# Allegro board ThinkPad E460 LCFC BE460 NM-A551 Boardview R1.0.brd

Outline 300.1 x 178 mm; copper layers: TOP, GND1, IN1, IN2, VCC, IN3, GND2, BOTTOM. Coordinates in mm from the lower left corner of the outline.
Outline path: 0,164 arc(0.59,165.41) 2,166 14.7,166 arc(15.41,166.29) 15.7,167 15.7,172 arc(16.29,173.41) 17.7,174 22.2,174 arc(22.55,174.15) 22.7,174.5 22.7,177 arc(22.99,177.71) 23.7,178 29.2,178 arc(29.55,177.85) 29.7,177.5 29.7,177.4 arc(29.85,177.05) 30.2,176.9 39.2,176.9 arc(39.55,177.05) 39.7,177.4 39.7,177.5 arc(39.85,177.85) 40.2,178 71.75,178 arc(72.46,177.71) 72.75,177 72.75,176 arc(73.04,175.29) 73.75,175 85.75,175 arc(86.46,175.29) 86.75,176 86.75,177 arc(87.04,177.71) 87.75,178 245.7,178 arc(247.11,177.41) 247.7,176 247.7,175 arc(247.99,174.29) 248.7,174 250.2,174 arc(250.91,173.71) 251.2,173 251.2,167 arc(251.49,166.29) 252.2,166 271.68,166 arc(273.1,165.41) 273.68,164 273.68,137.5 arc(273.98,136.79) 274.68,136.5 293.18,136.5 arc(294.6,135.91) 295.18,134.5 295.18,133.3 arc(296.16,130.34) 298.7,128.53 arc(298.95,128.34) 299.05,128.05 299.05,126.15 arc(298.9,125.8) 298.55,125.65 286.55,125.65 286.55,123.9 arc(286.7,123.55) 287.05,123.4 287.35,123.4 287.35,111.49 287.05,111.49 arc(286.7,111.34) 286.55,110.99 286.55,96.75 298.05,96.75 arc(298.4,96.6) 298.55,96.25 298.55,94.45 arc(298.26,93.74) 297.55,93.45 295.7,93.45 arc(294.35,92.1) 295.7,90.75 297.55,90.75 arc(298.26,90.46) 298.55,89.75 298.55,87.9 arc(298.4,87.55) 298.05,87.4 290.3,87.4 arc(289.8,87.9) 289.3,87.4 289.3,70.6 arc(289.8,70.1) 290.3,70.6 298.4,70.6 arc(298.75,70.45) 298.9,70.1 298.9,65.75 arc(298.75,65.4) 298.4,65.25 290.85,65.25 arc(290.4,64.8) 290.85,64.35 290.85,50.65 arc(290.4,50.2) 290.85,49.75 299.1,49.75 300.1,48.75 300.1,40.8 299.1,39.8 288.37,39.8 arc(287.87,39.3) 288.37,38.8 288.37,27.2 arc(287.87,26.7) 288.37,26.2 297.55,26.2 298.55,25.2 298.55,18.8 297.55,17.8 288.37,17.8 arc(287.87,17.3) 288.37,16.8 288.37,5.2 arc(287.87,4.7) 288.37,4.2 298.05,4.2 299.05,3.2 299.05,2 arc(298.46,0.59) 297.05,0 285.41,0 arc(284,0.59) 283.41,2 283.41,5.5 arc(282.82,6.91) 281.41,7.5 276.61,7.5 arc(275.2,8.09) 274.61,9.5 274.61,17.5 arc(274.9,18.21) 275.61,18.5 275.9,18.5 arc(276.25,18.65) 276.4,19 276.4,24 arc(276.25,24.35) 275.9,24.5 275.61,24.5 arc(274.9,24.79) 274.61,25.5 274.61,68.97 arc(274.33,69.69) 273.61,70 261.04,70 arc(260.33,70.29) 260.04,71 260.04,71.99 arc(259.89,72.35) 259.53,72.5 223.37,72.5 arc(222.98,72.34) 222.85,71.94 222.85,71.04 arc(222.54,70.28) 221.78,70 198.69,70 arc(197.96,69.72) 197.65,69 197.65,48.5 arc(197.06,47.09) 195.65,46.5 68.7,46.5 arc(67.99,46.21) 67.7,45.5 arc(67.41,44.79) 66.7,44.5 57.7,44.5 arc(56.99,44.79) 56.7,45.5 arc(56.41,46.21) 55.7,46.5 29.7,46.5 arc(28.29,47.09) 27.7,48.5 27.7,52.74 arc(28.14,54) 29.28,54.7 arc(40.89,59.22) 50.27,67.43 arc(50.88,67.79) 51.58,67.65 52.23,67.24 arc(52.41,67.14) 52.6,67.04 arc(56.47,68.36) 55.43,72.32 55.31,72.39 54.83,72.7 arc(54.4,73.27) 54.46,73.99 54.46,73.99 arc(52.82,108.97) 22.22,126 13.2,126 arc(12.05,126.37) 11.31,127.33 arc(11.28,127.42) 11.24,127.5 arc(10.87,127.87) 10.37,128 5.2,128 arc(4.85,128.15) 4.7,128.5 arc(4.55,128.85) 4.2,129 2,129 arc(0.59,129.59) 0,131 0,164

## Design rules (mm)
net group 5_20: nets +3VALW_LOGO +3VS_CMOS
net group +1.65V_LDO: nets +1.65V_LDO +3V_LDO
net group +3V_SPI: nets SPI_IO2 SPI_IO3
net group +3VL_AVCC: nets +3VL_AVCC EC_AGND
net group +5VS_CLASSD: nets +5VS_CLASSD N57924109
net group +5VS_HDMI: nets HDMI_CLK_CON HDMI_DAT_CON
net group ACIN: nets ACIN ACPRN
net group CLK-12: nets CLK_PCI_EC PCH_PCI_CLK_R
net group CPU_EDP_AUX: nets CPU_EDP_AUX CPU_EDP_AUX_CON
net group CPU_EDP_AUX#: nets CPU_EDP_AUX# CPU_EDP_AUX#_CON
net group CPU_EDP_TX0+: nets CPU_EDP_TX0+ CPU_EDP_TX0+_CON
net group CPU_EDP_TX0-: nets CPU_EDP_TX0- CPU_EDP_TX0-_CON
net group CPU_EDP_TX1+: nets CPU_EDP_TX1+ CPU_EDP_TX1+_CON
net group CPU_EDP_TX1-: nets CPU_EDP_TX1- CPU_EDP_TX1-_CON
net group DDRA_DQTODQS0: nets DDR_A_DQS0 DDR_A_DQS#0
net group DDRA_DQTODQS3: nets DDR_A_DQS3 DDR_A_DQS#3
net group DDRA_DQTODQS4: nets DDR_A_DQS4 DDR_A_DQS#4
net group DDRA_DQTODQS5: nets DDR_A_DQS5 DDR_A_DQS#5
net group DDRA_DQTODQS6: nets DDR_A_DQS6 DDR_A_DQS#6
net group DDRA_DQTODQS7: nets DDR_A_DQS7 DDR_A_DQS#7
net group DDRB_DQTODQS0: nets DDR_B_DQS0 DDR_B_DQS#0
net group DDRB_DQTODQS1: nets DDR_B_DQS1 DDR_B_DQS#1
net group DDRB_DQTODQS2: nets DDR_B_DQS2 DDR_B_DQS#2
net group DDRB_DQTODQS3: nets DDR_B_DQS3 DDR_B_DQS#3
net group DDRB_DQTODQS4: nets DDR_B_DQS4 DDR_B_DQS#4
net group DDRB_DQTODQS5: nets DDR_B_DQS5 DDR_B_DQS#5
net group DDRB_DQTODQS6: nets DDR_B_DQS6 DDR_B_DQS#6
net group DDRB_DQTODQS7: nets DDR_B_DQS7 DDR_B_DQS#7
net group DIFFPAIR13: nets USB20_N5 USB20_P5
net group DIFFPAIR20: nets CLK_PCIE_LAN CLK_PCIE_LAN#
net group DIFFPAIR21: nets CLK_PCIE_CR CLK_PCIE_CR#
net group DIFFPAIR22: nets CLK_PCIE_VGA CLK_PCIE_VGA#
net group DIFFPAIR23: nets CLK_PCIE_WLAN CLK_PCIE_WLAN#
net group DIFFPAIR94: nets HDMI_CLK HDMI_DAT
net group DIFFPAIR100: nets USB3P4_RXN USB3P4_RXP
net group DIFFPAIR101: nets N57771580 N57771583
net group DIFFPAIR104: nets PCIE3_PTX_DRX_N2 PCIE3_PTX_DRX_P2
net group DIFFPAIR105: nets PCIE4_PTX_DRX_N3 PCIE4_PTX_DRX_P3
net group DIFFPAIR106: nets PCIE1_PTX_DRX_N0 PCIE1_PTX_DRX_P0
net group DIFFPAIR107: nets PCIE2_PTX_DRX_N1 PCIE2_PTX_DRX_P1
net group DIFFPAIR108: nets PCIE4_CTX_C_DRX_N PCIE4_CTX_C_DRX_P
net group DISP_A0_L_C: nets DISP_A0N_L_C DISP_A0P_L_C
net group DISP_A1_L_C: nets DISP_A1N_L_C DISP_A1P_L_C
net group DOCK_AUXN: nets DOCK_AUXN DOCK_AUXN_RE
net group DOCK_AUXP: nets DOCK_AUXP DOCK_AUXP_RE
net group DOCK_TX0+: nets DOCK_TX0+ DOCK_TX0+_RE
net group DOCK_TX0-: nets DOCK_TX0- DOCK_TX0-_RE
net group DOCK_TX1: nets DOCK_TX1+ DOCK_TX1-
net group DOCK_TX1_R: nets DOCK_TX1+_R DOCK_TX1-_R
net group DOCK_TX_RE: nets DOCK_TX1+_RE DOCK_TX1-_RE
net group DP: nets DOCK_TX0+_R DOCK_TX0-_R
net group DP_RE_DP0: nets DP_RE_DP0N DP_RE_DP0P
net group DP_RE_DP1: nets DP_RE_DP1N DP_RE_DP1P
net group DP_USB3P4_TX: nets USB3P4_TXN USB3P4_TXP
net group DP_USB20_N3_OD: nets USB20_N3_OD USB20_P3_OD
net group GPIO15: nets GPIO15 SVI2_SVD
net group GPIO20: nets GPIO20 SVI2_SVC
net group HDA_SDOUT: nets HDA_SDOUT ME_FLASH
net group HDMI_TX0+_CON: nets HDMI_TX0+_CON HDMI_TX0+_REOUT
net group HDMI_TX0+_REIN: nets H_HDMI_TX0+ HDMI_TX0+_REIN
net group HDMI_TX0-_CON: nets HDMI_TX0-_CON HDMI_TX0-_REOUT
net group HDMI_TX0-_REIN: nets H_HDMI_TX0- HDMI_TX0-_REIN
net group HDMI_TX1+_CON: nets HDMI_TX1+_CON HDMI_TX1+_REOUT
net group HDMI_TX1+_REIN: nets H_HDMI_TX1+ HDMI_TX1+_REIN
net group HDMI_TX1-_CON: nets HDMI_TX1-_CON HDMI_TX1-_REOUT
net group HDMI_TX1-_REIN: nets H_HDMI_TX1- HDMI_TX1-_REIN
net group HDMI_TX2+_CON: nets HDMI_TX2+_CON HDMI_TX2+_REOUT
net group HDMI_TX2+_REIN: nets H_HDMI_TX2+ HDMI_TX2+_REIN
net group HDMI_TX2-_CON: nets HDMI_TX2-_CON HDMI_TX2-_REOUT
net group HDMI_TX2-_REIN: nets H_HDMI_TX2- HDMI_TX2-_REIN
net group HDMI_TXC+_CON: nets HDMI_TXC+_CON HDMI_TXC+_REOUT
net group HDMI_TXC+_REIN: nets H_HDMI_TXC+ HDMI_TXC+_REIN
net group HDMI_TXC-_CON: nets HDMI_TXC-_CON HDMI_TXC-_REOUT
net group HDMI_TXC-_REIN: nets H_HDMI_TXC- HDMI_TXC-_REIN
net group HP_OUTL: nets HP_OUTL N58599815
net group HP_OUTR: nets HP_OUTR N57919452
net group LAN_WAKE#: nets LAN_WAKE# LAN_WAKE#_R
net group N13756593: nets N13756593 N13756601
net group N13756597: nets N13756597 N13756610
net group N57924172: nets N57924172 N57924174
net group PC_BEEP: nets N57919838 PC_BEEP
net group PCH_PWROK: nets PCH_PWROK PWROK
net group PCIE3_CTX_C_DRX_N: nets PCIE3_CTX_C_DRX_N PCIE3_CTX_DRX_N
net group PCIE3_CTX_C_DRX_P: nets PCIE3_CTX_C_DRX_P PCIE3_CTX_DRX_P
net group PCIE4_CRX_DTX_N: nets PCIE4_CRX_DTX_N PCIE4_CRX_DTX_N_C
net group PCIE4_CRX_DTX_P: nets PCIE4_CRX_DTX_P PCIE4_CRX_DTX_P_C
net group PCIE4_CTX_C_DRX_: nets PCIE4_CTX_DRX_N PCIE4_CTX_DRX_P
net group PCIE6_CTX_C_DRX_N: nets PCIE6_CTX_C_DRX_N PCIE6_CTX_DRX_N
net group PCIE6_CTX_C_DRX_P: nets PCIE6_CTX_C_DRX_P PCIE6_CTX_DRX_P
net group PCIE_CRX_C_GTX_N0: nets PCIE_CRX_C_GTX_N0 PCIE_CRX_GTX_N0
net group PCIE_CRX_C_GTX_N1: nets PCIE_CRX_C_GTX_N1 PCIE_CRX_GTX_N1
net group PCIE_CRX_C_GTX_N2: nets PCIE_CRX_C_GTX_N2 PCIE_CRX_GTX_N2
net group PCIE_CRX_C_GTX_N3: nets PCIE_CRX_C_GTX_N3 PCIE_CRX_GTX_N3
net group PCIE_CRX_C_GTX_P0: nets PCIE_CRX_C_GTX_P0 PCIE_CRX_GTX_P0
net group PCIE_CRX_C_GTX_P1: nets PCIE_CRX_C_GTX_P1 PCIE_CRX_GTX_P1
net group PCIE_CRX_C_GTX_P2: nets PCIE_CRX_C_GTX_P2 PCIE_CRX_GTX_P2
net group PCIE_CRX_C_GTX_P3: nets PCIE_CRX_C_GTX_P3 PCIE_CRX_GTX_P3
net group PCIE_CTX_C_GRX_0: nets PCIE_CTX_C_GRX_N0 PCIE_CTX_C_GRX_P0
net group PCIE_CTX_C_GRX_1: nets PCIE_CTX_C_GRX_N1 PCIE_CTX_C_GRX_P1
net group PCIE_CTX_C_GRX_2: nets PCIE_CTX_C_GRX_N2 PCIE_CTX_C_GRX_P2
net group PCIE_CTX_C_GRX_3: nets PCIE_CTX_C_GRX_N3 PCIE_CTX_C_GRX_P3
net group PCIE_WLAN: nets PCIE3_CRX_DTX_N PCIE3_CRX_DTX_P
net group PORTB_L: nets N57919402 PORTB_L
net group PS8713_RX1_C_N: nets PS8713_RX1_C_N USB3P1_RXN_CON
net group PS8713_RX1_C_P: nets PS8713_RX1_C_P USB3P1_RXP_CON
net group PS8713_RX1_R: nets PS8713_RX1_N_R PS8713_RX1_P_R
net group PS8713_RX2_C_N: nets PS8713_RX2_C_N USB30_RX_N2_CON
net group PS8713_RX2_C_P: nets PS8713_RX2_C_P USB30_RX_P2_CON
net group REMOTE1: nets REMOTE1+ REMOTE1-
net group REMOTE2: nets REMOTE2+ REMOTE2-
net group SATA_PRX_C_DTX_N0: nets SATA_PRX_C_DTX_N0 SATA_PRX_DTX_N0
net group SATA_PRX_C_DTX_P0: nets SATA_PRX_C_DTX_P0 SATA_PRX_DTX_P0
net group SATA_PTX_C_DRX_N0: nets SATA_PTX_C_DRX_N0 SATA_PTX_DRX_N0
net group SATA_PTX_C_DRX_P0: nets SATA_PTX_C_DRX_P0 SATA_PTX_DRX_P0
net group TP_RESET: nets TP_RESET TP_REST
net group USB3_RX4_OD: nets USB3_RX4_N_OD USB3_RX4_P_OD
net group USB3_TX1_REOUT: nets USB3_TX1+_REOUT USB3_TX1-_REOUT
net group USB3_TX4_OD: nets USB3_TX4_N_OD USB3_TX4_P_OD
net group USB3P1_RX: nets USB3P1_RXN USB3P1_RXP
net group USB3P1_RX_R: nets USB3P1_RXN_R USB3P1_RXP_R
net group USB3P1_TX: nets USB3_TX1+_REIN USB3_TX1-_REIN
net group USB3P1_TX1: nets USB3P1_TXN USB3P1_TXP
net group USB3P1_TX_C: nets USB3P1_TXN_C USB3P1_TXP_C
net group USB3P1_TX_CON: nets USB3P1_TXN_CON USB3P1_TXP_CON
net group USB3P1_TX_R: nets USB3P1_TXN_R USB3P1_TXP_R
net group USB3P2_RX_R: nets USB3P2_RXN_R USB3P2_RXP_R
net group USB3P2_RXN: nets N57772807 USB3P2_RXN
net group USB3P2_RXP: nets N57772804 USB3P2_RXP
net group USB3P2_TX_R: nets USB3P2_TXN_R USB3P2_TXP_R
net group USB3P2_TXN: nets USB3_TX2-_REIN USB3P2_TXN
net group USB3P2_TXP: nets USB3_TX2+_REIN USB3P2_TXP
net group USB3P4_RX_C: nets USB3P4_RXN_C USB3P4_RXP_C
net group USB3P4_TX_C: nets USB3P4_TXN_C USB3P4_TXP_C
net group USB20_7_COMS: nets USB20_N6_CMOS USB20_P6_CMOS
net group USB20_N0: nets USB20_N0 USB20_N0_CON
net group USB20_N1: nets USB20_N1 USB20_N1_CON
net group USB20_N2_C: nets USB20_N2_C USB20_N2_CONN
net group USB20_P0: nets USB20_P0 USB20_P0_CON
net group USB20_P1: nets USB20_P1 USB20_P1_CON
net group USB20_P2_C: nets USB20_P2_C USB20_P2_CONN
net group USB30_TX_2_CON: nets USB3_TX2+_REOUT USB3_TX2-_REOUT
net group USB30_TX_N2_CON: nets USB3P2_TXN_C USB30_TX_N2_CON
net group USB30_TX_P2_CON: nets USB3P2_TXP_C USB30_TX_P2_CON
net group VCC_SENSE: nets N62685817 VCC_SENSE
net group VCCGT_SENSE: nets N62959739 VCCGT_SENSE
net group VSS_SENSE: nets N62687376 VSS_SENSE
net group VSUM: nets VSUM+ VSUM-
net group +3VALW_LAN: nets N19577505
net group +VCC_ST: nets THRMTRIP#
net group AUDIO_IHDA: nets HDA_BCLK HDA_RST# HDA_SYNC PCH_HDA_RST# PCH_HDA_SDIN0 PCH_HDA_SDIN0_R PCH_HDA_SDOUT PCH_HDA_SYNC
net group BEEP#: nets BEEP# N57919809 PCH_BEEP
net group CONTROL_LINK: nets CL_CLK_WLAN
net group DIFFPAIR77: nets USB20_P2
net group DMIC-12: nets DMIC_CLK DMIC_DATA MIC_CLK_R
net group DOCK_AUXN_CONN: nets DOCK_AUXN_CONN DOCK_AUXN_R DP_RE_AUXN
net group DOCK_AUXP_CONN: nets DOCK_AUXP_CONN DOCK_AUXP_R DP_RE_AUXP
net group EDP: nets CPU_EDP_HPD
net group FBA_RST#: nets FBA_RST# N13756920 N13756934
net group LAN2: nets RJ45_TXD0N RJ45_TXD0P RJ45_TXD1N RJ45_TXD1P RJ45_TXD2N RJ45_TXD2P RJ45_TXD3N RJ45_TXD3P
net group PCIE6_CRX_DTX_: nets PCIE6_CRX_DTX_P
net group PCIE_CR: nets PCIE6_CRX_DTX_N
net group PWR: nets +3VALW_GS +3VS_VDDIO +5VS_AVDD AOU_CTL3 APDIN P3 SPI_IO2_4MB SPI_IO2_8MB SPI_IO3_4MB SPI_IO3_8MB VSYSTEM
net group RTC: nets PCH_RTCRST# PCH_RTCX1 PCH_RTCX2
net group S8: nets SUSCLK_32K
net group S12: nets CLKREQ_PCIE5_CR# VR_SVID_ALRT#_R VR_SVID_CLK VR_SVID_DAT
net group S13.5: nets DDR3_DRAMRST# H_PROCHOT_EC VR_HOT# VR_HOT#_R
net group S18: nets H_PECI H_THERMTRIP# PECI
net group S20: nets DIFFCLK_BIASREF SM_RCOMP0 SM_RCOMP1 SM_RCOMP2
net group SMBUS: nets EC_SMB_CK1 EC_SMB_CK3 EC_SMB_DA1 EC_SMB_DA3 PCH_SMB_CLK PCH_SMB_DATA PM_SMB_CLK PM_SMB_DAT SMBCLK SMBDAT
net group SPI-12: nets SPI_CLK SPI_CLK_4MB SPI_CLK_8MB SPI_FSCK
net group SPK_L1-: nets SPK_L1-
net group SPK_L2+: nets SPK_L2+
net group SPK_R1-: nets SPK_R1-
net group SPK_R2+: nets SPK_R2+
net group USB20: nets USB20_N2 USB20_N3 USB20_N4_TPANEL USB20_N4_TPANEL_C USB20_N6 USB20_N8 USB20_P3 USB20_P4_TPANEL USB20_P4_TPANEL_C USB20_P6 USB20_P8
net group USB30: nets PS8713_RX2_N_R PS8713_RX2_P_R USB3_TX4_N_C USB3_TX4_P_C USB3P3_RXN USB3P3_RXN_C USB3P3_RXP USB3P3_RXP_C USB3P3_TXN USB3P3_TXN_C USB3P3_TXP USB3P3_TXP_C USB3P4_RE_RXN USB3P4_RE_RXN_R USB3P4_RE_RXP USB3P4_RE_RXP_R USB3P4_RE_TXN USB3P4_RE_TXN_R USB3P4_RE_TXP USB3P4_RE_TXP_R USB3P4_RXN_R USB3P4_RXP_R USB3P4_TXN_R USB3P4_TXP_R

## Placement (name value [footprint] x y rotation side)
C1  0.1U_0402_10V7-K  [C_0402]  42.15 127.59 180 top
C2  2200P_0402_50V7-K  [C_0402]  39.48 126.78 270 top
C3  2200P_0402_50V7-K  [C_0402]  39.86 124.75 270 top
C4  100P_0402_50V8-J  [C_0402]  163.02 110.37 0 top
C5  100P_0402_50V8-J  [C_0402]  4.81 132.37 270 top
C8  1U_0402_6.3V6-K  [C_0402]  70.97 119.03 0 bottom
C9  4.7U_0603_10V6-K  [C_0603]  72.63 116.62 0 bottom
C10  1U_0402_6.3V6-K  [C_0402]  65.91 123.71 135 bottom
C11  4.7U_0603_10V6-K  [C_0603]  62.35 117.62 315 bottom
C12  4.7U_0805_25V6-K  [C_0805]  61.99 111.95 45 bottom
C13  0.1U_0402_10V7-K  [C_0402]  55.42 121.77 225 bottom
C14  0.1U_0402_10V7-K  [C_0402]  54.79 122.4 225 bottom
C15  0.1U_0402_10V7-K  [C_0402]  54.15 123.04 225 bottom
C16  0.1U_0402_10V7-K  [C_0402]  53.52 123.67 225 bottom
C17  0.1U_0402_10V7-K  [C_0402]  56.82 120.37 225 bottom
C18  0.1U_0402_10V7-K  [C_0402]  56.18 121.01 225 bottom
C19  10U_0805_10V6-K  [C_0805]  251.57 80.33 90 bottom
C20  10U_0805_10V6-K  [C_0805]  245.98 80.3 90 bottom
C21  1U_0402_10V6K  [C_0402]  249.28 80.17 90 bottom
C22  0.1U_0402_10V7-K  [C_0402]  250.17 80.17 90 bottom
C23  1000P_0402_50V7-K  [C_0402]  247.5 80.17 90 bottom
C24  .01U_0402_16V7-K  [C_0402]  226.93 81.06 270 bottom
C25  .01U_0402_16V7-K  [C_0402]  227.95 81.06 270 bottom
C26  .01U_0402_16V7-K  [C_0402]  230.36 81.06 270 bottom
C27  .01U_0402_16V7-K  [C_0402]  231.38 81.06 270 bottom
C28  0.1U_0402_10V7-K  [C_0402]  207.88 99.52 90 top
C29  .01U_0402_16V7-K  [C_0402]  205.07 92.05 180 top
C30  0.1U_0402_10V7-K  [C_0402]  201.89 97 0 top
C31  0.1U_0402_10V7-K  [C_0402]  201.73 94.77 0 top
C32  0.1U_0402_10V7-K  [C_0402]  201.91 95.71 0 top
C33  0.1U_0402_10V7-K  [C_0402]  201.71 93.45 0 top
C34  0.1U_0402_10V7-K  [C_0402]  225.25 99.47 90 top
C35  .01U_0402_16V7-K  [C_0402]  221.06 91.37 270 top
C36  0.1U_0402_10V7-K  [C_0402]  219.03 97.44 0 top
C37  0.1U_0402_10V7-K  [C_0402]  219.06 96.12 0 top
C38  0.1U_0402_10V7-K  [C_0402]  217.43 92.44 90 top
C39  0.1U_0402_10V7-K  [C_0402]  219.54 92.45 90 top
C40  .01U_0402_16V7-K  [C_0402]  275.07 125.27 90 bottom
C41  1U_0402_6.3V6-K  [C_0402]  275.96 125.27 90 bottom
C44  100P_0402_50V8J  [C_0402]  123.93 69.43 90 bottom
C45  100P_0402_50V8J  [C_0402]  124.95 69.43 90 bottom
C50  0.1U_0402_10V6-K  [C_0402]  124.99 157.27 270 top
C51  10U_0603_6.3V6-M  [C_0603]  123.94 157.22 270 top
C52  0.1U_0402_10V7-K  [C_0402]  190.15 74.07 0 top
C53  0.1U_0402_10V7-K  [C_0402]  296.58 42.32 0 top
C67  10U_0603_6.3V6-M  [C_0603]  249.6 152.09 180 top
C68  0.1U_0402_10V7-K  [C_0402]  141.82 69.3 270 top
C69  1U_0402_6.3V6-K  [C_0402]  219.58 138.15 90 top
C70  0.1U_0402_10V7-K  [C_0402]  221.34 130.79 270 top
C71  1000P_0402_25V7-K  [C_0402]  218.8 133.08 270 top
C72  100P_0402_50V8-J  [C_0402]  217.91 133.08 270 top
C73  1U_0402_6.3V6-K  [C_0402]  217.04 138.1 90 top
C74  0.1U_0402_10V7-K  [C_0402]  216.92 130.11 270 top
C75  .01U_0402_16V7-K  [C_0402]  268.28 129.83 180 top
C85  0.1U_0402_10V7-K  [C_0402]  272.32 114.33 0 top
C86  0.1U_0402_10V7-K  [C_0402]  272.32 115.22 0 top
C115  0.1U_0402_10V7-K  [C_0402]  253.52 154.08 0 top
C116  0.1U_0402_10V7-K  [C_0402]  253.52 153.19 0 top
C118  1000P_0402_50V7-K  [C_0402]  279.89 30.18 90 bottom
C119  0.1U_0402_10V7-K  [C_0402]  279.76 21.32 270 bottom
C120  1000P_0402_50V7-K  [C_0402]  283.39 25.94 180 bottom
C121  0.1U_0402_10V7-K  [C_0402]  277.4 37.95 90 bottom
C122  0.1U_0402_10V7-K  [C_0402]  277.4 39.78 270 bottom
C123  150U_B2_6.3VM_R35M  [C_B2]  282.43 28.86 270 bottom
C124  0.1U_0402_10V7-K  [C_0402]  278.87 37.93 90 bottom
C125  0.1U_0402_10V7-K  [C_0402]  277.71 17.71 90 bottom
C126  0.1U_0402_10V7-K  [C_0402]  279.23 17.66 90 bottom
C127  470P_0402_50V7-K  [C_0402]  279.33 26.32 180 bottom
C128  150U_B2_6.3VM_R35M  [C_B2]  279.75 9.95 0 top
C129  470P_0402_50V7-K  [C_0402]  283.32 10.83 90 bottom
C130  0.1U_0402_10V7-K  [C_0402]  278.87 39.76 270 bottom
C131  0.1U_0402_10V7-K  [C_0402]  277.71 19.54 270 bottom
C132  0.1U_0402_10V7-K  [C_0402]  279.23 19.49 270 bottom
C174  47P_0402_50V8-J  [C_0402]  60.62 113.75 45 bottom
C175  2200P_0402_50V7-K  [C_0402]  61.25 113.12 45 bottom
C176  47P_0402_50V8-J  [C_0402]  58.71 115.66 45 bottom
C177  2200P_0402_50V7-K  [C_0402]  61.63 116.69 315 bottom
C178  47P_0402_50V8-J  [C_0402]  72.63 114.59 0 bottom
C179  2200P_0402_50V7-K  [C_0402]  72.63 115.48 0 bottom
C180  2200P_0402_50V7-K  [C_0402]  57.39 116.89 45 bottom
C181  47P_0402_50V8-J  [C_0402]  59.14 119.04 45 bottom
C182  47P_0402_50V8-J  [C_0402]  267.52 154.46 180 top
C183  2200P_0402_50V7-K  [C_0402]  269.53 154.46 0 top
C184  0.1U_0402_10V7-K  [C_0402]  266.01 117.85 270 top
C185  0.1U_0402_10V7-K  [C_0402]  261.03 123.62 0 top
C186  0.1U_0402_10V7-K  [C_0402]  261.03 122.22 0 top
C187  0.1U_0402_10V7-K  [C_0402]  261.03 121.33 0 top
C188  0.1U_0402_10V7-K  [C_0402]  261.03 119.93 0 top
C189  .01U_0402_16V7-K  [C_0402]  269.49 125.7 90 top
C194  47UF_0805_6.3V  [C_0805]  104.78 128.65 180 top
C197  0.1U_0201_6.3V6K  [C_0201]  119.75 132.04 90 top
C200  0.1U_0201_6.3V6K  [C_0201]  114.14 128.02 90 top
C201  0.1U_0201_6.3V6K  [C_0201]  115.33 128.23 90 top
C202  2200P_0402_50V7-K  [C_0402]  253.87 80.62 90 bottom
C203  47P_0402_50V8-J  [C_0402]  252.98 80.62 90 bottom
C204  2200P_0402_50V7-K  [C_0402]  239.06 80.18 0 bottom
C205  47P_0402_50V8-J  [C_0402]  242 80.18 180 bottom
C206  2200P_0402_50V7-K  [C_0402]  57.96 110.48 315 top
C207  2200P_0402_50V7-K  [C_0402]  72.56 117.65 0 bottom
C747  2200P_0402_25V7-K  [C_0402]  76.49 118.02 0 top
C748  0.1U_0402_6.3V7-K  [C_0402]  74.62 114.52 180 top
C749  10U_0402_6.3V  [C_0402]  78.63 114.45 180 top
C750  1U_0402_6.3V6-K  [C_0402]  180.33 158.54 0 top
C751  4.7U_0603_10V6-K  [C_0603]  178.94 153.72 180 top
C8496  0.1U_0402_10V6-K  [C_0402]  132.62 161.07 0 top
C8497  0.1U_0402_10V6-K  [C_0402]  129.85 156.24 180 top
C8498  0.1U_0402_10V6-K  [C_0402]  126.41 163.37 0 top
C8499  10U_0603_6.3V6-M  [C_0603]  132.38 162.34 0 top
C8527  10U_0402_6.3V  [C_0402]  175.66 104.08 270 top
C8534  10U_0402_6.3V  [C_0402]  76.32 123.97 0 top
C8535  0.1U_0402_10V7-K  [C_0402]  78.33 119.22 90 top
C8536  4.7U_0603_6.3V6-K  [C_0603]  139.54 155.86 0 top
C8537  0.1U_0402_10V7-K  [C_0402]  142.73 157.21 270 top
C8538  0.22U_0402_10V6-K  [C_0402]  144.7 163.19 90 top
C8542  0.1U_0402_10V6-K  [C_0402]  129.56 132.81 270 top
CA1  0.1U_0402_10V7-K  [C_0402]  194.62 59.65 180 top
CA2  4.7U_0603_10V6-K  [C_0603]  176.64 53.04 270 top
CA3  4.7U_0603_10V6-K  [C_0603]  177.86 53.04 270 top
CA4  0.1U_0402_10V7-K  [C_0402]  185.78 61.55 90 top
CA5  0.1U_0402_10V7-K  [C_0402]  189.1 61.74 90 top
CA6  0.1U_0402_10V7-K  [C_0402]  192.06 54.36 180 top
CA7  4.7U_0603_10V6-K  [C_0603]  193.52 53.85 0 top
CA8  0.1U_0402_10V7-K  [C_0402]  180.96 53.19 270 top
CA9  1U_0402_6.3V6-K  [C_0402]  180.07 53.19 270 top
CA10  0.1U_0402_10V7-K  [C_0402]  178.8 57.36 180 top
CA11  2.2U_0402_6.3V6-M  [C_0402]  179.04 56.22 180 top
CA12  0.1U_0402_10V7-K  [C_0402]  191.62 51.29 270 top
CA13  1U_0402_6.3V6-K  [C_0402]  180.91 58.22 90 top
CA14  1U_0402_6.3V6-K  [C_0402]  182.35 61.88 180 top
CA15  1U_0402_6.3V6-K  [C_0402]  182.96 55.68 180 top
CA16  0.1U_0402_10V7-K  [C_0402]  192.34 61.94 180 top
CA17  1U_0402_6.3V6-K  [C_0402]  181.52 60.99 0 top
CA18  2.2U_0402_6.3V6-M  [C_0402]  182.43 59.98 180 top
CA19  0.1U_0402_10V7-K  [C_0402]  172.93 55.99 0 top
CA22  0.1U_0402_10V7-K  [C_0402]  193.53 67.04 270 top
CA23  0.1U_0402_10V7-K  [C_0402]  191.51 62.82 0 top
CA24  0.1U_0402_10V7-K  [C_0402]  192.34 61.06 180 top
CA25  470P_0402_50V7-K  [C_0402]  190.48 67.04 270 top
CA26  470P_0402_50V7-K  [C_0402]  191.62 67.04 270 top
CA27  470P_0402_50V7-K  [C_0402]  189.47 67.04 270 top
CA28  470P_0402_50V7-K  [C_0402]  188.45 67.04 270 top
CA29  2.2U_0402_6.3V6-K  [C_0402]  182.81 52.28 90 top
CA30  2.2U_0402_6.3V6-K  [C_0402]  181.85 51.19 270 top
CA31  10U_0603_6.3V6-M  [C_0603]  184.77 51.4 270 top
CA32  10U_0603_6.3V6-M  [C_0603]  186.04 51.4 270 top
CA40  150P_0402_50V8-J  [C_0402]  189.34 51.29 270 top
CA42  4.7U_0603_10V6-K  [C_0603]  190.93 58.07 0 top
CA43  47P_0402_50V8-J  [C_0402]  190.23 53.07 270 top
CC1  1U_0402_10V6K  [C_0402]  135.45 135.99 270 top
CC2  1U_0402_10V6K  [C_0402]  128.57 132.81 270 top
CC3  5.6P_0402_50V8-D  [C_0402]  124.37 143.75 270 top
CC4  5.6P_0402_50V8-D  [C_0402]  124.37 144.99 90 top
CC5  1U_0402_10V6K  [C_0402]  134.55 137.19 180 top
CC6  12P_0402_50V8-J  [C_0402]  91.17 115.98 90 bottom
CC7  12P_0402_50V8-J  [C_0402]  91.17 115.09 270 bottom
CC9  100P_0402_25V8J  [C_0402]  73.9 116.95 270 top
CC18  0.1U_0402_10V7-K  [C_0402]  98.41 127.79 0 top
CC19  0.1U_0402_10V7-K  [C_0402]  98.41 128.68 0 top
CC20  0.1U_0402_10V7-K  [C_0402]  89.14 123.73 0 bottom
CC21  0.1U_0402_10V7-K  [C_0402]  89.14 124.62 0 bottom
CC22  0.1U_0402_10V6-K  [C_0402]  207.75 120.12 270 bottom
CC23  0.1U_0402_10V7-K  [C_0402]  91.17 119.92 0 bottom
CC24  0.1U_0402_10V7-K  [C_0402]  89.14 119.41 0 bottom
CC25  0.1U_0402_10V7-K  [C_0402]  129.94 128.44 0 top
CC26  0.1U_0402_10V7-K  [C_0402]  138.85 128.42 180 top
CC46  1U_0201_6.3V6  [C_0201]  104.39 129.8 90 top
CC47  1U_0201_6.3V6  [C_0201]  112.43 124.79 0 top
CC49  1U_0201_6.3V6  [C_0201]  105.21 126.69 0 top
CC50  1U_0201_6.3V6  [C_0201]  105.81 129.24 90 top
CC52  1U_0201_6.3V6  [C_0201]  106.85 126.63 270 top
CC58  1U_0201_6.3V6  [C_0201]  113.56 128.05 90 top
CC59  1U_0201_6.3V6  [C_0201]  114.27 126.63 270 top
CC60  1U_0201_6.3V6  [C_0201]  114.76 135.5 180 top
CC61  1U_0201_6.3V6  [C_0201]  111.03 135.43 180 top
CC68  1U_0402_10V6K  [C_0402]  98.71 124.75 0 top
CC69  1U_0402_10V6K  [C_0402]  95.92 126.02 0 top
CC70  1U_0402_10V6K  [C_0402]  104.82 124.71 0 top
CC86  0.1U_0402_10V7-K  [C_0402]  89.14 121.19 0 bottom
CC87  0.1U_0402_10V7-K  [C_0402]  89.14 122.08 0 bottom
CC88  0.1U_0402_10V7-K  [C_0402]  91.17 123.48 0 bottom
CC89  0.1U_0402_10V7-K  [C_0402]  91.17 122.59 0 bottom
CC90  0.1U_0402_10V7-K  [C_0402]  91.17 120.81 0 bottom
CC91  0.1U_0402_10V7-K  [C_0402]  89.14 118.52 0 bottom
CC92  0.1U_0402_10V7-K  [C_0402]  91.17 126.14 0 bottom
CC93  0.1U_0402_10V7-K  [C_0402]  91.17 125.25 0 bottom
CC94  1U_0402_10V6K  [C_0402]  119.49 112.68 90 top
CC95  1U_0201_6.3V6  [C_0201]  109.15 126.51 180 top
CC96  1U_0201_6.3V6  [C_0201]  112.41 126.7 270 top
CC97  1U_0201_6.3V6  [C_0201]  107.46 126.65 270 top
CC99  1U_0201_6.3V6  [C_0201]  113.58 126.63 270 top
CC101  1U_0402_10V6K  [C_0402]  174.64 104.08 270 top
CC102  100P_0402_25V8J  [C_0402]  74.91 116.95 270 top
CC205  10U_0603_6.3V6-M  [C_0603]  114.8 110.56 180 top
CC206  10U_0603_6.3V6-M  [C_0603]  113.56 102.1 180 top
CC207  10U_0603_6.3V6-M  [C_0603]  114.47 109.34 180 top
CC208  10U_0603_6.3V6-M  [C_0603]  114.47 108.12 180 top
CC209  10U_0603_6.3V6-M  [C_0603]  113.02 105.61 90 top
CC210  10U_0603_6.3V6-M  [C_0603]  113.02 104.64 270 top
CC211  10U_0603_6.3V6-M  [C_0603]  114.65 113.46 180 top
CC212  10U_0603_6.3V6-M  [C_0603]  112.9 119.99 90 top
CC213  10U_0603_6.3V6-M  [C_0603]  73.96 110.03 90 bottom
CC214  10U_0603_6.3V6-M  [C_0603]  78.02 109.09 0 top
CC215  10U_0603_6.3V6-M  [C_0603]  78.02 106.62 0 top
CC216  10U_0603_6.3V6-M  [C_0603]  78.02 107.84 0 top
CC217  10U_0603_6.3V6-M  [C_0603]  77.67 105.48 270 top
CC218  10U_0603_6.3V6-M  [C_0603]  72.23 110.38 90 bottom
CC219  10U_0603_6.3V6-M  [C_0603]  109.14 122.22 90 top
CC220  10U_0603_6.3V6-M  [C_0603]  110.36 122.22 90 top
CC221  10U_0603_6.3V6-M  [C_0603]  110 120.9 270 top
CC222  10U_0603_6.3V6-M  [C_0603]  108.78 120.9 270 top
CC223  10U_0603_6.3V6-M  [C_0603]  105.48 122.22 90 top
CC224  10U_0603_6.3V6-M  [C_0603]  111.22 120.9 270 top
CC225  10U_0603_6.3V6-M  [C_0603]  103.85 120.26 0 top
CC235  10U_0603_6.3V6-M  [C_0603]  104.95 113.81 0 top
CC236  10U_0603_6.3V6-M  [C_0603]  112.16 116.48 180 top
CC237  10U_0603_6.3V6-M  [C_0603]  112.16 117.72 180 top
CC238  10U_0603_6.3V6-M  [C_0603]  104.95 116.33 0 top
CC239  10U_0603_6.3V6-M  [C_0603]  104.95 115.08 0 top
CC240  10U_0603_6.3V6-M  [C_0603]  112.16 113.97 180 top
CC241  10U_0603_6.3V6-M  [C_0603]  112.16 115.24 180 top
CC242  10U_0603_6.3V6-M  [C_0603]  107.36 112.37 270 top
CC243  1U_0201_6.3V6-M  [C_0201]  103.23 113.61 270 top
CC244  1U_0201_6.3V6-M  [C_0201]  108.22 113.56 90 top
CC245  1U_0201_6.3V6-M  [C_0201]  108.91 113.56 90 top
CC246  1U_0201_6.3V6-M  [C_0201]  107.56 113.53 90 top
CC247  1U_0201_6.3V6-M  [C_0201]  108.93 117.55 270 top
CC248  1U_0201_6.3V6-M  [C_0201]  108.3 117.55 270 top
CC249  1U_0201_6.3V6-M  [C_0201]  107.64 117.55 270 top
CC250  1U_0201_6.3V6-M  [C_0201]  112.13 118.69 0 top
CC251  1U_0201_6.3V6-M  [C_0201]  100.77 119.12 90 top
CC252  1U_0201_6.3V6-M  [C_0201]  113.9 115.01 270 top
CC253  1U_0201_6.3V6-M  [C_0201]  114.54 115.01 270 top
CC254  1U_0201_6.3V6-M  [C_0201]  99.8 122.55 90 top
CC255  1U_0201_6.3V6-M  [C_0201]  103.36 117.72 90 top
CC256  1U_0201_6.3V6-M  [C_0201]  100.82 114.88 270 top
CC257  1U_0201_6.3V6-M  [C_0201]  102.84 115.2 180 top
CC266  10U_0603_6.3V6-M  [C_0603]  104.95 117.57 0 top
CC267  10U_0603_6.3V6-M  [C_0603]  106.09 112.37 270 top
CC268  10U_0603_6.3V6-M  [C_0603]  112.31 112.37 270 top
CC269  10U_0603_6.3V6-M  [C_0603]  108.6 112.37 270 top
CC270  10U_0603_6.3V6-M  [C_0603]  111.09 112.37 270 top
CC271  10U_0603_6.3V6-M  [C_0603]  109.85 112.37 270 top
CC272  10U_0603_6.3V6-M  [C_0603]  104.82 112.37 270 top
CC273  10U_0603_6.3V6-M  [C_0603]  92.34 70.54 90 bottom
CC274  10U_0603_6.3V6-M  [C_0603]  91.14 70.54 90 bottom
CC275  10U_0603_6.3V6-M  [C_0603]  87.31 70.44 180 bottom
CC276  10U_0603_6.3V6-M  [C_0603]  97.8 69.25 0 bottom
CC277  10U_0603_6.3V6-M  [C_0603]  89.57 70.54 90 bottom
CC278  10U_0603_6.3V6-M  [C_0603]  87.31 69.17 180 bottom
CC279  10U_0603_6.3V6-M  [C_0603]  88.37 70.54 90 bottom
CC280  10U_0603_6.3V6-M  [C_0603]  97.8 70.51 0 bottom
CC281  10U_0603_6.3V6-M  [C_0603]  104.82 107.13 0 top
CC282  10U_0603_6.3V6-M  [C_0603]  104.82 104.69 0 top
CC283  1U_0201_6.3V6-M  [C_0201]  108.99 98.2 180 top
CC284  1U_0201_6.3V6-M  [C_0201]  109.24 99.35 180 top
CC285  1U_0201_6.3V6-M  [C_0201]  111.2 98.33 0 top
CC286  1U_0201_6.3V6-M  [C_0201]  110.47 98.17 90 top
CC287  1U_0201_6.3V6-M  [C_0201]  111.2 98.97 0 top
CC288  1U_0201_6.3V6-M  [C_0201]  111.2 99.6 0 top
CC289  1U_0201_6.3V6-M  [C_0201]  111.2 100.24 0 top
CC290  1U_0201_6.3V6-M  [C_0201]  109.54 100.11 0 top
CC291  1U_0201_6.3V6-M  [C_0201]  106.79 98.17 90 top
CC292  1U_0201_6.3V6-M  [C_0201]  105.3 98.08 180 top
CC293  1U_0201_6.3V6-M  [C_0201]  105.68 99.35 180 top
CC294  1U_0201_6.3V6-M  [C_0201]  104.79 100.49 180 top
CC329  1U_0201_6.3V6-M  [C_0201]  101.75 123.35 180 top
CC330  1U_0201_6.3V6-M  [C_0201]  101.75 122.59 180 top
CC331  1U_0201_6.3V6-M  [C_0201]  103.23 123.6 90 top
CC332  1U_0201_6.3V6-M  [C_0201]  102.86 120.66 180 top
CC333  1U_0201_6.3V6-M  [C_0201]  104.84 121.18 0 top
CC334  1U_0201_6.3V6-M  [C_0201]  113.14 122.8 90 top
CC335  1U_0201_6.3V6-M  [C_0201]  112.5 122.8 90 top
CC336  1U_0201_6.3V6-M  [C_0201]  114.24 112.55 180 top
CC337  1U_0201_6.3V6-M  [C_0201]  116.82 112.43 270 top
CC338  1U_0201_6.3V6-M  [C_0201]  113.9 119.58 270 top
CC339  1U_0201_6.3V6-M  [C_0201]  114.24 111.79 180 top
CC340  1U_0201_6.3V6-M  [C_0201]  118.29 123.43 180 top
CC341  1U_0201_6.3V6-M  [C_0201]  118.29 120.68 180 top
CC342  1U_0201_6.3V6-M  [C_0201]  119.47 122.96 90 top
CC343  1U_0201_6.3V6-M  [C_0201]  118.29 117.02 180 top
CC344  1U_0201_6.3V6-M  [C_0201]  118.32 113.37 180 top
CC500  1U_0201_6.3V6-M  [C_0201]  113.27 115.01 270 top
CC501  1U_0201_6.3V6-M  [C_0201]  98.28 113.86 270 top
CC502  1U_0201_6.3V6-M  [C_0201]  109.58 117.55 270 top
CC503  1U_0201_6.3V6-M  [C_0201]  109.57 113.56 90 top
CC504  1U_0201_6.3V6-M  [C_0201]  103.52 114.33 180 top
CC505  1U_0201_6.3V6-M  [C_0201]  103.41 115.95 90 top
CC506  1U_0201_6.3V6-M  [C_0201]  100.12 116.19 0 top
CC507  1U_0201_6.3V6-M  [C_0201]  97.52 119.2 270 top
CC508  1U_0201_6.3V6-M  [C_0201]  102.9 120.09 180 top
CC509  1U_0201_6.3V6-M  [C_0201]  102 114.21 180 top
CC510  1U_0201_6.3V6-M  [C_0201]  102 113.57 180 top
CC511  1U_0201_6.3V6-M  [C_0201]  101.75 117.51 180 top
CC512  1U_0201_6.3V6-M  [C_0201]  102.84 116.11 180 top
CC514  1U_0201_6.3V6-M  [C_0201]  113.9 117.6 90 top
CC515  1U_0201_6.3V6-M  [C_0201]  114.54 117.6 90 top
CC516  1U_0201_6.3V6-M  [C_0201]  99.13 111.92 0 top
CC517  1U_0201_6.3V6-M  [C_0201]  99.13 111.28 0 top
CC518  1U_0201_6.3V6-M  [C_0201]  115.13 116.11 0 top
CC519  1U_0201_6.3V6-M  [C_0201]  115.27 115.17 0 top
CC520  10U_0603_6.3V6-M  [C_0603]  105.71 100.6 90 top
CC521  10U_0603_6.3V6-M  [C_0603]  110.89 101.75 180 top
CC522  1U_0201_6.3V6-M  [C_0201]  103.38 106.93 180 top
CC523  1U_0201_6.3V6-M  [C_0201]  103.52 103.28 180 top
CC524  1U_0201_6.3V6-M  [C_0201]  104.29 102.39 180 top
CC525  1U_0201_6.3V6-M  [C_0201]  104.29 101.76 180 top
CC526  1U_0201_6.3V6-M  [C_0201]  114.89 121.1 180 top
CC527  5P_0402_50V9-C  [C_0402]  101.37 132.35 180 top
CC528  5P_0402_50V9-C  [C_0402]  136.7 117.75 0 top
CC529  5P_0402_50V9-C  [C_0402]  139.24 142.79 0 top
CC530  1U_0201_6.3V6  [C_0201]  113.11 130.22 0 top
CC531  1U_0201_6.3V6  [C_0201]  110.24 128.72 0 top
CC532  1U_0201_6.3V6  [C_0201]  107.07 129.56 0 top
CC535  47UF_0805_6.3V  [C_0805]  94.95 129.08 0 top
CC536  47UF_0805_6.3V  [C_0805]  86.05 137.57 270 top
CC537  47P_0402_50V8-J  [C_0402]  128.49 136.34 0 top
CC538  47P_0402_50V8-J  [C_0402]  192.42 55.62 0 top
CC539  0.1U_0402_10V6-K  [C_0402]  109.44 130.53 0 top
CC540  0.1U_0402_10V6-K  [C_0402]  134.74 143.71 90 top
CD1  2.2U_0402_6.3V6-K  [C_0402]  162.54 89.01 270 top
CD2  0.022U_0402_25V7-K  [C_0402]  158.86 88.09 90 top
CD3  0.1U_0402_10V7-K  [C_0402]  161.65 89.01 270 top
CD8  1U_0402_6.3VA-K  [C_0402]  171.3 126.52 0 top
CD9  1U_0402_6.3VA-K  [C_0402]  171.36 125.51 0 top
CD10  1U_0402_6.3VA-K  [C_0402]  170.03 123.35 180 top
CD11  1U_0402_6.3VA-K  [C_0402]  170.03 128.56 180 top
CD12  0.022U_0402_25V7-K  [C_0402]  158.43 131.41 270 top
CD13  10U_0603_6.3V6-M  [C_0603]  170.99 117.63 0 top
CD14  10U_0603_6.3V6-M  [C_0603]  164.26 118.14 180 top
CD15  10U_0603_6.3V6-M  [C_0603]  165.34 116.24 0 top
CD16  10U_0603_6.3V6-M  [C_0603]  170.99 119.54 0 top
CD17  0.1U_0402_10V7-K  [C_0402]  172.19 128.43 0 top
CD18  2.2U_0402_6.3V6-K  [C_0402]  160.2 130.5 90 top
CD19  10U_0603_6.3V6-M  [C_0603]  162.73 115.22 180 top
CD20  10U_0603_6.3V6-M  [C_0603]  170.99 115.73 0 top
CD21  10U_0603_6.3V6-M  [C_0603]  162.6 120.43 180 top
CD22  330U_D2_2V_Y  [C_D2]  163.18 123.1 90 top
CD23  1U_0402_6.3VA-K  [C_0402]  171.69 155.79 90 top
CD24  1U_0402_6.3VA-K  [C_0402]  170.67 155.79 90 top
CD25  1U_0402_6.3VA-K  [C_0402]  166.1 155.79 90 top
CD26  1U_0402_6.3VA-K  [C_0402]  164.95 155.79 90 top
CD29  2.2U_0402_6.3V6-K  [C_0402]  149.9 153.46 0 top
CD30  0.1U_0402_10V6-K  [C_0402]  149.9 152.57 0 top
CD31  0.022U_0402_25V7-K  [C_0402]  145.9 88.09 90 top
CD32  0.1U_0402_10V7-K  [C_0402]  148.57 89.01 270 top
CD33  2.2U_0402_6.3V6-K  [C_0402]  149.46 89.01 270 top
CD38  1U_0402_6.3VA-K  [C_0402]  159.32 118.27 180 top
CD39  1U_0402_6.3VA-K  [C_0402]  159.32 117.38 180 top
CD40  1U_0402_6.3VA-K  [C_0402]  158.1 124.37 180 top
CD41  1U_0402_6.3VA-K  [C_0402]  159.43 119.3 0 top
CD42  10U_0603_6.3V6-M  [C_0603]  159.5 120.7 180 top
CD43  10U_0603_6.3V6-M  [C_0603]  153.41 122.6 180 top
CD44  10U_0603_6.3V6-M  [C_0603]  153.41 131.11 180 top
CD45  10U_0603_6.3V6-M  [C_0603]  157.59 127.79 180 top
CD46  10U_0603_6.3V6-M  [C_0603]  151 112.7 270 top
CD47  10U_0603_6.3V6-M  [C_0603]  166.49 128.06 0 top
CD48  10U_0603_6.3V6-M  [C_0603]  159.5 122.09 180 top
CD49  0.1U_0402_10V7-K  [C_0402]  172.19 129.32 0 top
CD51  1U_0402_6.3VA-K  [C_0402]  151.87 155.79 90 top
CD52  1U_0402_6.3VA-K  [C_0402]  172.59 155.8 90 top
CD53  1U_0402_6.3VA-K  [C_0402]  152.77 155.8 90 top
CD54  1U_0402_6.3VA-K  [C_0402]  150.98 155.79 90 top
CD55  10U_0603_6.3V6-M  [C_0603]  149.85 155.3 90 top
CD56  10U_0603_6.3V6-M  [C_0603]  169.41 155.68 90 top
CD57  2.2U_0402_6.3V6-K  [C_0402]  167.24 152.56 0 top
CD58  0.1U_0402_10V6-K  [C_0402]  167.24 153.45 0 top
CD59  0.1U_0402_10V7-K  [C_0402]  159.19 99.6 180 top
CD60  0.1U_0402_10V7-K  [C_0402]  173.97 100.67 90 top
CE1  47P_0402_50V8-J  [C_0402]  183.5 133.69 90 top
CE2  0.1U_0402_25V6-K  [C_0402]  196.58 119.72 90 top
CE3  1000P_0402_50V7-K  [C_0402]  197.47 119.72 90 top
CE4  0.1U_0402_25V6-K  [C_0402]  178.92 133.69 90 top
CE5  0.1U_0402_25V6-K  [C_0402]  180.96 133.69 90 top
CE6  0.1U_0402_25V6-K  [C_0402]  186.16 112.12 270 top
CE7  0.1U_0402_25V6-K  [C_0402]  174.28 126.4 0 top
CE8  0.1U_0402_25V6-K  [C_0402]  185.53 133.69 90 top
CE9  0.1U_0402_25V6-K  [C_0402]  186.54 133.69 90 top
CE10  0.1U_0402_25V6-K  [C_0402]  196.5 128.91 0 top
CE11  1U_0402_10V6-K  [C_0402]  175.19 124.62 180 top
CE12  100P_0402_50V8-J  [C_0402]  188.45 133.69 90 top
CE13  220P_0402_50V7-K  [C_0402]  174.26 118.74 0 top
CE14  0.1U_0402_25V6-K  [C_0402]  190.74 133.69 90 top
CE16  100P_0402_50V8-J  [C_0402]  196.5 116.11 0 top
CE17  47P_0402_50V8-J  [C_0402]  199.55 122.84 0 top
CG1  0.1U_0402_10V6-K  [C_0402]  172.5 113.44 0 top
CG2  .01U_0402_16V7-K  [C_0402]  175.76 111.17 90 top
CG3  10U_0603_6.3V6-M  [C_0603]  173.16 107.36 180 top
CG4  .01U_0402_16V7-K  [C_0402]  174.33 113.33 0 top
CL1  0.1U_0402_10V7-K  [C_0402]  248.44 94.9 0 top
CL2  0.1U_0402_10V7-K  [C_0402]  248.44 94.01 0 top
CL3  1U_0402_6.3V6-K  [C_0402]  253.35 89.62 90 bottom
CL4  0.1U_0402_10V7-K  [C_0402]  254.74 89.62 90 bottom
CL5  0.1U_0402_10V7-K  [C_0402]  256.85 92.23 180 bottom
CL6  22U_0805_6.3V6M  [C_0805]  258.01 90.08 180 bottom
CL7  15P_0402_50V8-J  [C_0402]  255.71 87.28 180 top
CL8  15P_0402_50V8-J  [C_0402]  256.57 87.28 0 top
CL9  0.1U_0402_10V7-K  [C_0402]  268 95.76 90 bottom
CL10  1000P_1808_3KV7k~D  [C_1808]  281.81 87.93 90 bottom
CL11  0.1U_0402_10V7-K  [C_0402]  284.91 68.99 270 top
CL12  .01U_0402_16V7-K  [C_0402]  281.83 92.78 90 top
CL13  1U_0402_10V6K  [C_0402]  266.64 96.06 180 bottom
CL17  .01U_0402_16V7-K  [C_0402]  245.4 97.7 0 bottom
CM1  0.1U_0402_10V7-K  [C_0402]  265.03 151.11 270 top
CM2  0.1U_0402_10V7-K  [C_0402]  263.63 151.11 270 top
CM3  0.1U_0402_10V7-K  [C_0402]  261.73 151.11 270 top
CM4  0.1U_0402_10V7-K  [C_0402]  260.33 151.11 270 top
CM5  0.1U_0402_10V7-K  [C_0402]  267.66 145.31 180 top
CM6  0.1U_0402_10V7-K  [C_0402]  267.65 143.97 180 top
CM7  0.1U_0402_10V7-K  [C_0402]  268.56 141.4 180 top
CM8  0.1U_0402_10V7-K  [C_0402]  268.56 142.91 180 top
CM9  0.1U_0402_10V7-K  [C_0402]  257.46 139.48 0 top
CM10  .01U_0402_16V7-K  [C_0402]  257.46 138.59 0 top
CM11  2.2U_0402_6.3V6-K  [C_0402]  256.01 146.9 90 top
CM12  2.2U_0402_6.3V6-K  [C_0402]  266.74 146.48 0 top
CM13  0.1U_0402_10V7-K  [C_0402]  264.4 138.92 270 top
CM14  0.1U_0402_10V7-K  [C_0402]  264.4 137.09 90 top
CM15  0.1U_0402_10V7-K  [C_0402]  263 138.92 270 top
CM16  0.1U_0402_10V7-K  [C_0402]  263 137.09 90 top
CM17  0.1U_0402_10V7-K  [C_0402]  261.98 138.92 270 top
CM18  0.1U_0402_10V7-K  [C_0402]  261.98 137.09 90 top
CM19  0.1U_0402_10V7-K  [C_0402]  260.59 138.92 270 top
CM20  0.1U_0402_10V7-K  [C_0402]  260.59 137.09 90 top
CRE1  0.1U_0402_10V7-K  [C_0402]  240.32 86.65 0 top
CRE3  0.1U_0402_10V7-K  [C_0402]  240.32 85.76 0 top
CRE5  0.1U_0402_10V7-K  [C_0402]  240.32 88.42 0 top
CRE7  0.1U_0402_10V7-K  [C_0402]  240.32 87.54 0 top
CRE9  0.1U_0402_10V7-K  [C_0402]  240.32 90.2 0 top
CRE11  0.1U_0402_10V7-K  [C_0402]  240.32 89.31 0 top
CRE13  0.1U_0402_10V7-K  [C_0402]  240.32 84.87 0 top
CRE14  0.1U_0402_10V7-K  [C_0402]  240.32 83.98 0 top
CRE17  0.1U_0402_10V7-K  [C_0402]  248.14 84.28 90 bottom
CRE18  0.1U_0402_10V7-K  [C_0402]  244.71 89.77 270 bottom
CRE19  0.1U_0402_10V7-K  [C_0402]  247.25 84.28 90 bottom
CRE20  0.1U_0402_10V7-K  [C_0402]  245.6 84.28 90 bottom
CRE21  .01U_0402_16V7-K  [C_0402]  247.25 89.77 270 bottom
CRE22  .01U_0402_16V7-K  [C_0402]  248.14 89.77 270 bottom
CRE23  0.1U_0402_10V7-K  [C_0402]  244.71 84.28 90 bottom
CRE24  .01U_0402_16V7-K  [C_0402]  245.85 89.77 270 bottom
CRF1  2200P_0402_50V7-K  [C_0402]  171.36 122.46 0 top
CRF2  47P_0402_50V8-J  [C_0402]  171.36 121.32 0 top
CRF3  2200P_0402_50V7-K  [C_0402]  156.83 114.97 0 top
CRF4  47P_0402_50V8-J  [C_0402]  158.1 129.32 0 top
CV1  .01U_0402_16V7-K  [C_0402]  49.34 157.32 180 top
CV2  0.1U_0402_10V7-K  [C_0402]  47.1 150.12 270 top
CV3  2.2U_0402_6.3V6-K  [C_0402]  50.57 154.48 90 top
CV4  2.2U_0402_6.3V6-K  [C_0402]  49.71 155.17 180 top
CV5  2.2U_0402_6.3V6-K  [C_0402]  50 143.79 180 top
CV6  2.2U_0402_6.3V6-K  [C_0402]  49.31 146.23 180 top
CV7  2.2U_0402_6.3V6-K  [C_0402]  48.36 147.88 0 top
CV8  10U_0603_6.3V6-M  [C_0603]  50.39 157.93 90 top
CV9  1U_0402_10V6-K  [C_0402]  62.21 150.58 90 top
CV10  1U_0402_10V6-K  [C_0402]  61.2 150.58 90 top
CV17  10U_0603_6.3V6-M  [C_0603]  46.39 171.85 90 bottom
CV18  10U_0603_6.3V6-M  [C_0603]  45.09 171.89 90 bottom
CV19  1U_0402_10V6-K  [C_0402]  46.95 170.49 180 bottom
CV20  10U_0603_6.3V6-M  [C_0603]  43.92 169.39 90 top
CV21  1U_0402_10V6-K  [C_0402]  45.07 169.63 90 top
CV22  1U_0402_10V6-K  [C_0402]  51.28 130.79 90 bottom
CV24  1U_0402_10V6-K  [C_0402]  49.21 131.88 270 bottom
CV25  0.1U_0402_10V7-K  [C_0402]  48.32 131.88 270 bottom
CV26  10U_0603_6.3V6-M  [C_0603]  61.26 149 0 top
CV27  1U_0402_10V6-K  [C_0402]  59.65 146.49 270 top
CV28  1U_0402_10V6-K  [C_0402]  62.18 154.05 180 top
CV29  10U_0603_6.3V6-M  [C_0603]  52.23 145.01 0 top
CV30  10U_0603_6.3V6-M  [C_0603]  54.96 145.2 270 top
CV31  1U_0402_10V6-K  [C_0402]  52.85 146.53 0 top
CV32  1U_0402_10V6-K  [C_0402]  57.88 146.23 270 top
CV33  1U_0402_10V6-K  [C_0402]  51.98 143.03 0 top
CV34  1U_0402_10V6-K  [C_0402]  56.99 146.23 270 top
CV35  1U_0402_10V6-K  [C_0402]  51.08 146.53 0 top
CV36  1U_0402_10V6-K  [C_0402]  51.97 143.94 0 top
CV37  2.2U_0402_6.3V6-K  [C_0402]  57.25 152.45 0 top
CV38  2.2U_0402_6.3V6-K  [C_0402]  59.92 155.37 180 top
CV39  2.2U_0402_6.3V6-K  [C_0402]  56.41 147.55 0 top
CV40  2.2U_0402_6.3V6-K  [C_0402]  60.22 154.08 180 top
CV41  2.2U_0402_6.3V6-K  [C_0402]  56.44 157.94 270 top
CV42  2.2U_0402_6.3V6-K  [C_0402]  57.76 156.64 270 top
CV43  2.2U_0402_6.3V6-K  [C_0402]  53.18 155.83 90 top
CV44  2.2U_0402_6.3V6-K  [C_0402]  52.6 148.59 0 top
CV45  10U_0603_6.3V6-M  [C_0603]  56.04 150.98 0 top
CV46  10U_0603_6.3V6-M  [C_0603]  50.71 150.98 0 top
CV47  10U_0603_6.3V6-M  [C_0603]  54.96 156.68 270 top
CV48  10U_0603_6.3V6-M  [C_0603]  72.37 156.37 180 top
CV49  10U_0603_6.3V6-M  [C_0603]  72.37 155.1 180 top
CV50  10U_0603_6.3V6-M  [C_0603]  58.46 150.98 0 top
CV51  2.2U_0402_6.3V6-K  [C_0402]  56.44 148.69 0 top
CV52  2.2U_0402_6.3V6-K  [C_0402]  51.58 149.63 0 top
CV53  2.2U_0402_6.3V6-K  [C_0402]  51.46 155.4 270 top
CV54  2.2U_0402_6.3V6-K  [C_0402]  57.25 154.48 180 top
CV55  2.2U_0402_6.3V6-K  [C_0402]  52.98 150.98 0 top
CV56  2.2U_0402_6.3V6-K  [C_0402]  61.24 155.02 0 top
CV57  2.2U_0402_6.3V6-K  [C_0402]  51.61 153.32 270 top
CV58  2.2U_0402_6.3V6-K  [C_0402]  61.29 155.88 90 top
CV59  10U_0603_6.3V6-M  [C_0603]  54.96 151.73 270 top
CV60  10U_0603_6.3V6-M  [C_0603]  54.96 154.27 270 top
CV61  1U_0402_10V6-K  [C_0402]  54.96 148.49 90 top
CV62  1U_0402_10V6-K  [C_0402]  60.37 152.76 180 top
CV63  1U_0402_10V6-K  [C_0402]  50.44 153.27 270 top
CV64  0.1U_0402_10V7-K  [C_0402]  52.78 153.37 0 top
CV65  0.1U_0402_10V7-K  [C_0402]  59.05 157.71 270 top
CV66  10U_0603_6.3V6-M  [C_0603]  60.93 144.56 0 top
CV67  1U_0402_10V6-K  [C_0402]  60.97 145.6 0 top
CV70  1U_0402_10V6-K  [C_0402]  61.24 152.76 0 top
CV71  0.1U_0402_10V7-K  [C_0402]  56.11 144.96 270 top
CV72  1U_0402_10V6-K  [C_0402]  50.15 134.6 270 bottom
CV73  1U_0402_10V6-K  [C_0402]  48.11 134.6 270 bottom
CV74  120P_0402_50V8-J  [C_0402]  65.14 168.33 270 top
CV75  68P_0402_50V8-J  [C_0402]  62.48 167.41 90 top
CV76  0.1U_0402_10V7-K  [C_0402]  49.26 172.37 90 top
CV77  0.1U_0402_10V7-K  [C_0402]  44.05 173.26 270 top
CV78  10U_0603_6.3V6-M  [C_0603]  14.53 130.92 270 bottom
CV79  1U_0402_10V6-K  [C_0402]  28.63 130.93 270 bottom
CV80  1U_0402_10V6-K  [C_0402]  23.61 144.24 90 bottom
CV81  1U_0402_10V6-K  [C_0402]  19.74 130.55 270 bottom
CV82  1U_0402_10V6-K  [C_0402]  16.56 144.24 90 bottom
CV83  1U_0402_10V6-K  [C_0402]  26.09 144.24 90 bottom
CV84  0.1U_0402_10V7-K  [C_0402]  24.5 144.24 90 bottom
CV85  0.1U_0402_10V7-K  [C_0402]  18.49 144.21 90 bottom
CV86  0.1U_0402_10V7-K  [C_0402]  24.44 130.55 270 bottom
CV87  0.1U_0402_10V7-K  [C_0402]  17.96 130.55 270 bottom
CV88  0.1U_0402_10V7-K  [C_0402]  27.74 130.93 270 bottom
CV89  10U_0603_6.3V6-M  [C_0603]  19.92 144.15 90 top
CV90  1U_0402_10V6-K  [C_0402]  26.85 130.55 270 top
CV91  1U_0402_10V6-K  [C_0402]  25.83 130.55 270 top
CV92  1U_0402_10V6-K  [C_0402]  23.8 130.55 270 top
CV93  1U_0402_10V6-K  [C_0402]  24.06 144.24 90 top
CV94  1U_0402_10V6-K  [C_0402]  27.61 144.24 90 top
CV95  0.1U_0402_10V7-K  [C_0402]  26.09 144.24 90 top
CV96  0.1U_0402_10V7-K  [C_0402]  16.56 130.55 270 top
CV97  0.1U_0402_10V7-K  [C_0402]  16.56 144.24 90 top
CV98  0.1U_0402_10V7-K  [C_0402]  17.96 144.24 90 top
CV99  0.1U_0402_10V7-K  [C_0402]  15.67 130.55 270 top
CV100  0.1U_0402_10V7-K  [C_0402]  21.62 144.24 90 bottom
CV103  0.1U_0402_10V7-K  [C_0402]  22.79 144.24 90 top
CV104  .01U_0402_16V7-K  [C_0402]  21.13 129.64 90 top
CV105  10U_0603_6.3V6-M  [C_0603]  19.92 163.8 90 top
CV106  1U_0402_10V6-K  [C_0402]  24.49 164.23 90 top
CV107  1U_0402_10V6-K  [C_0402]  15.27 150.77 270 top
CV108  1U_0402_10V6-K  [C_0402]  18.09 164.18 90 top
CV109  1U_0402_10V6-K  [C_0402]  18.47 151.05 270 top
CV110  1U_0402_10V6-K  [C_0402]  26.47 164.18 90 top
CV111  0.1U_0402_10V7-K  [C_0402]  24.31 150.87 270 top
CV112  0.1U_0402_10V7-K  [C_0402]  27.87 164.18 90 top
CV113  0.1U_0402_10V7-K  [C_0402]  21.06 164.18 90 top
CV114  0.1U_0402_10V7-K  [C_0402]  25.78 150.87 270 top
CV115  0.1U_0402_10V7-K  [C_0402]  16.82 150.74 270 top
CV116  10U_0603_6.3V6-M  [C_0603]  13.19 161.7 180 bottom
CV117  1U_0402_10V6-K  [C_0402]  20.12 150.87 270 bottom
CV118  1U_0402_10V6-K  [C_0402]  17.02 151 270 bottom
CV119  1U_0402_10V6-K  [C_0402]  22.02 163.93 90 bottom
CV120  1U_0402_10V6-K  [C_0402]  13.63 152.03 180 bottom
CV121  1U_0402_10V6-K  [C_0402]  23.29 164.18 90 bottom
CV122  0.1U_0402_10V7-K  [C_0402]  24.44 164.18 90 bottom
CV123  0.1U_0402_10V7-K  [C_0402]  18.47 151.05 270 bottom
CV124  0.1U_0402_10V7-K  [C_0402]  26.47 164.18 90 bottom
CV125  0.1U_0402_10V7-K  [C_0402]  13.67 153.7 180 bottom
CV126  0.1U_0402_10V7-K  [C_0402]  27.55 164.2 90 bottom
CV127  0.1U_0402_10V7-K  [C_0402]  22.4 150.82 270 top
CV130  0.1U_0402_10V7-K  [C_0402]  23.5 150.87 270 bottom
CV131  .01U_0402_16V7-K  [C_0402]  20.04 166.03 0 bottom
CV132  0.1U_0402_10V7-K  [C_0402]  63.35 133.94 90 bottom
CV133  0.1U_0402_10V7-K  [C_0402]  62.47 133.94 90 bottom
CV134  0.1U_0402_10V7-K  [C_0402]  61.45 133.94 90 bottom
CV135  0.1U_0402_10V7-K  [C_0402]  60.56 133.94 90 bottom
CV136  0.1U_0402_10V7-K  [C_0402]  69.2 131.53 90 top
CV137  0.1U_0402_10V7-K  [C_0402]  68.31 131.53 90 top
CV138  0.1U_0402_10V7-K  [C_0402]  67.16 131.53 90 top
CV139  0.1U_0402_10V7-K  [C_0402]  66.28 131.53 90 top
CV140  0.1U_0402_10V7-K  [C_0402]  83.69 137.36 0 top
CV141  0.1U_0402_10V7-K  [C_0402]  85.27 143.54 180 top
CV142  0.1U_0402_10V7-K  [C_0402]  48.24 172.37 90 top
CV143  22P_0402_50V8-J  [C_0402]  70.45 145.31 180 bottom
CV144  22P_0402_50V8-J  [C_0402]  70.45 143.4 180 bottom
CV145  1U_0402_10V6-K  [C_0402]  60.87 146.79 0 top
CV148  0.1U_0402_10V7-K  [C_0402]  57.64 129.01 270 bottom
CV149  0.1U_0402_10V7-K  [C_0402]  21.09 168.67 0 bottom
CV150  0.1U_0402_10V7-K  [C_0402]  26.18 168.85 0 bottom
CV151  0.1U_0402_10V7-K  [C_0402]  26.18 171.52 0 bottom
CV152  10U_0603_6.3V6-M  [C_0603]  25.95 172.63 0 bottom
CV153  0.1U_0402_10V7-K  [C_0402]  68.43 149.82 90 bottom
CV154  0.1U_0402_10V7-K  [C_0402]  69.09 153.75 90 bottom
CV155  0.1U_0402_10V7-K  [C_0402]  68.43 152.91 270 bottom
CV156  0.1U_0402_10V7-K  [C_0402]  68.43 149 270 bottom
CV160  0.22U_0402_10V6-K  [C_0402]  46.49 131.38 180 bottom
CV161  4.7U_0603_6.3V6-K  [C_0603]  48.17 127.29 270 bottom
CV162  0.1U_0402_10V7-K  [C_0402]  47.99 128.66 90 bottom
CV163  1U_0402_6.3V6-K  [C_0402]  63.62 173.73 270 bottom
CV164  0.1U_0402_10V7-K  [C_0402]  62.41 172.75 180 bottom
CV165  820P_0402_50V7-K  [C_0402]  59.72 172.75 0 bottom
CV166  0.1U_0402_10V7-K  [C_0402]  48.32 172.37 180 bottom
CV169  .01U_0402_16V7-K  [C_0402]  71.86 158.35 270 top
CV175  0.1U_0402_10V7-K  [C_0402]  59.89 172.61 0 top
CV176  1U_0402_6.3V6-K  [C_0402]  59 175.56 180 top
CV177  0.1U_0402_10V7-K  [C_0402]  64.93 171.86 0 top
CV178  820P_0402_50V7-K  [C_0402]  62.54 172.63 180 top
CV179  0.22U_0402_10V6-K  [C_0402]  59.07 173.33 180 top
D1  -  [PESD5V0U2BT_SOT23-3]  62.5 124.09 315 bottom
D2  -  [RCLAMP0524PATCT_SLP2510P8-10-9]  284.3 52.37 90 bottom
D3  -  [RCLAMP0524PATCT_SLP2510P8-10-9]  283.87 58.59 270 top
D4  -  [AZC199-02SPR7G_SOT23-3]  196.58 105.04 0 top
D5  -  [PJSOT24C_SOT23-3]  267.8 151.85 270 top
D6  -  [RB751V-40_SOD323-2]  230.11 173.13 0 bottom
D7  -  [RCLAMP0524PATCT_SLP2510P8-10-9]  282.66 33.31 90 bottom
D8  CM1293A_SC-74  [IP4223CZ6_SO6-6]  281.37 35.33 0 top
D9  CM1293A_SC-74  [IP4223CZ6_SO6-6]  283.75 12.23 180 top
D10  -  [RCLAMP0524PATCT_SLP2510P8-10-9]  282.66 13.62 90 bottom
D11  -  [RCLAMP0524PATCT_SLP2510P8-10-9]  285.91 60.5 90 top
D15  CM1293A_SC-74  [IP4223CZ6_SO6-6]  279.1 118.24 90 top
D16  -  [RCLAMP0524PATCT_SLP2510P8-10-9]  281.6 111.43 90 top
D17  -  [RCLAMP0524PATCT_SLP2510P8-10-9]  280.72 116.86 270 top
D18  -  [RCLAMP0524PATCT_SLP2510P8-10-9]  281.72 122.22 90 top
D22  -  [RB521CS-30GT2RA_VMN2-2]  252.84 149.29 90 top
D23  RB521CM_30  [RB521CS-30GT2RA_VMN2-2]  79.09 112.05 180 top
D24  -  [RB491D_SOT23-3]  280.42 48.55 270 bottom
D25  -  [RB521CS-30GT2RA_VMN2-2]  251.81 149.3 90 top
D59  RB521CM_30  [RB521CS-30GT2RA_VMN2-2]  181.17 141.37 270 top
D60  RB521CM_30  [RB521CS-30GT2RA_VMN2-2]  174.3 116.02 0 top
D61  RB521CM_30  [RB521CS-30GT2RA_VMN2-2]  176.4 141.37 0 top
D62  RB521CM_30  [RB521CS-30GT2RA_VMN2-2]  180.2 141.37 180 top
D63  RB521CM_30  [RB521CS-30GT2RA_VMN2-2]  194.17 136.27 180 top
D64  RB521CM_30  [RB521CS-30GT2RA_VMN2-2]  191.41 136.19 0 top
DA1  -  [BAT54CW_SOT323-3]  172.8 62.29 270 top
DA3  -  [RB751V-40_SOD323-2]  193.44 52.18 0 top
DA4  -  [RB751V-40_SOD323-2]  193.44 50.04 0 top
DA5  -  [RB751V-40_SOD323-2]  179.12 69.12 0 bottom
DC23  -  [RB521CS-30GT2RA_VMN2-2]  91.45 100.38 180 top
DEV1  -  [RB751V-40_SOD323-2]  188.01 137.45 0 top
DL1  -  [RCLAMP0524PATCT_SLP2510P8-10-9]  263.44 95.17 90 top
DL2  -  [RCLAMP0524PATCT_SLP2510P8-10-9]  271.31 97.2 90 top
DL3  -  [BS401N_1206-2]  260.34 89.86 270 bottom
DL4  -  [BS401N_1206-2]  257.72 84.61 0 bottom
DL5  -  [BS401N_1206-2]  284.6 91.49 270 bottom
DL6  -  [BS401N_1206-2]  281.3 82.98 90 bottom
DV1  -  [RB751V-40_SOD323-2]  63.54 128.56 180 bottom
DV2  -  [RB751V-40_SOD323-2]  72.62 159.13 90 bottom
DV6  -  [RB751V-40_SOD323-2]  54.92 175.6 0 top
F1  1812L110PR 1.1A  [F_SMD1812P110TF]  281.02 122.87 180 bottom
F2  0.5A_8V_KMC3S050RY  [F_KMC3S050RY]  282.94 47.3 90 bottom
FD1  CF  [FIDUCIAL_C40M80]  277.74 27.99 90 top
FD2  CF  [FIDUCIAL_C40M80]  55.75 52.75 90 top
FD3  CF  [FIDUCIAL_C40M80]  240.51 163.8 90 top
FD4  CF  [FIDUCIAL_C40M80]  240.66 164.38 90 bottom
FD5  CF  [FIDUCIAL_C40M80]  10.98 131.17 180 bottom
FD6  CF  [FIDUCIAL_C40M80]  279.06 10.49 180 bottom
H1  -  [PAD_C6P0D3P2]  118.06 144.3 0 top
H2  -  [PAD_C6P0D3P2]  96.05 144.3 0 top
H3  -  [PAD_C6P0D3P2]  96.05 89.3 0 top
H4  -  [PAD_C6P0D3P2]  118.06 89.3 0 top
H5  PAD_CT8P0B6P0D3P3  [PAD_C6P0D3P3]  54.95 169 0 top
H6  PAD_CT8P0B6P0D3P3  [PAD_C6P0D3P3]  37.45 138.5 0 top
H7  PAD_CT8P0B6P0D3P3  [PAD_C6P0D3P3]  72.45 138.5 0 top
H8  -  [PAD_C8P0D2P5]  108.7 55 0 top
H10  -  [PAD_CT8P0B6P0D2P5]  289.7 45.5 0 top
H11  -  [PAD_C5P0D2P5]  292.4 22 0 top
H12  -  [PAD_C8P0D2P5]  291 132 0 top
H13  -  [PAD_O3P9X2P7D3P9X2P7N]  287.6 22 90 top
H14  -  [PAD_CT6P0B8P0D2P5]  31.7 50.5 0 top
H15  PAD_shapeT8P0X10P5CB8P0D2P5  [PAD_SHAPET8P0X10P5CB8P0D2P5]  62.7 92.85 0 top
H16  -  [PAD_O2P3X3P5D2P3X3P5N]  38.7 50.5 108 top
H17  -  [PAD_CT6P0SHAPEB8P0X6P65D2P5]  34.7 174 0 top
H18  PAD_C8P0D2P5  [PAD_C8P0D3P0]  244.7 171.5 0 top
H19  -  [PAD_C5P0D2P3]  267.02 72.4 0 top
H20  -  [PAD_C6P0D3P3]  259.7 129 0 top
H21  PAD_shapeT8P0X10P5CB8P0D2P5  [PAD_SHAPET8P0X10P5CB8P0D2P5]  206.7 132.47 0 top
H24  -  [PAD_C8P0D2P5]  134.7 171.5 0 top
H25  -  [PAD_C2P3D2P3N]  279.9 132 0 top
H26  -  [PAD_O4P7X3P5D4P7X3P5N]  285.01 132 90 top
H27  PAD_C5P0D2P5  [PAD_C5P0D3P0]  289.7 92.1 0 top
H28  -  [PAD_C6P0D2P3]  209.7 74.4 0 top
